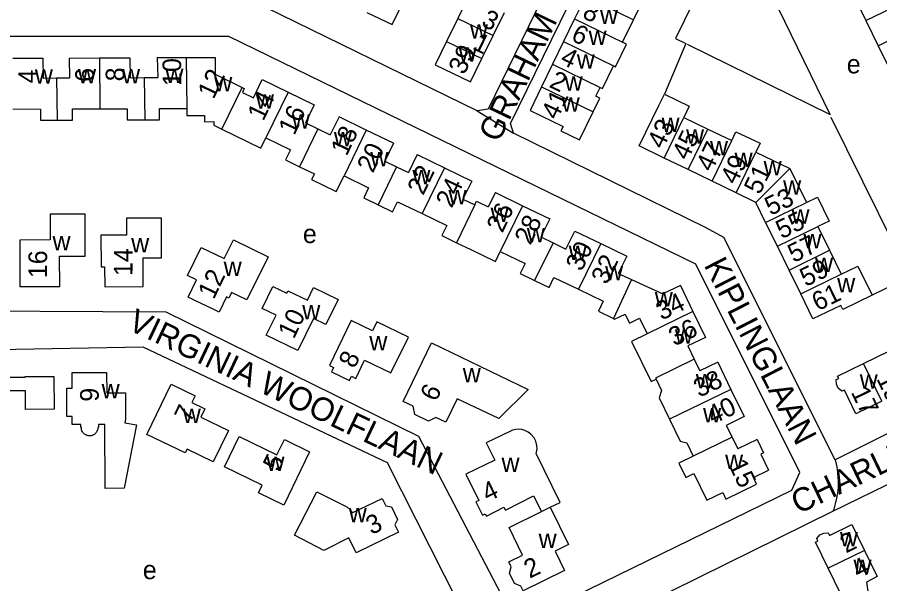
# Model space of a CAD drawing. Extents: x 159441 to 162086, y 388175 to 389787.
# Drawn here: x 161138.4 to 161323.2, y 388573.1 to 388694.6 of the extents above; entities that cross this region are included whole.
import ezdxf

# ---------------------------------------------------------------- set-up
doc = ezdxf.new("R2010")
doc.units = 0
for name, color, linetype in [('BLT_Basislijn', 7, 'Continuous'), ('BLT_Bebouwing', 7, 'Continuous'), ('BLT_Centroide', 7, 'Continuous'), ('BLT_Huisnummer', 7, 'Continuous'), ('BLT_Huisnummer_ tussenligend', 7, 'Continuous'), ('BLT_Onderverdeling_panden', 7, 'Continuous'), ('BLT_Straatnaam', 7, 'Continuous'), ('BLT_Vlakafsluiter', 7, 'Continuous')]:
    doc.layers.add(name, color=color, linetype=linetype)

msp = doc.modelspace()

# ---------------------------------------------------------------- linework, layer by layer
at = {"layer": 'BLT_Basislijn'}
for p, q in [((161165.42, 388623.86), (161116.75, 388622.95)), ((161217.72, 388599.05), (161165.42, 388623.86)), ((161335.21, 388610.56), (161313.61, 388599.68)), ((161237.07, 388560.94), (161217.72, 388599.05)), ((161313.14, 388588.69), (161333.92, 388598.92)), ((161221.35, 388543.5), (161313.14, 388588.69))]:
    msp.add_line(p, q, dxfattribs=at)
for points in [[(161177.47, 388769.07), (161262.68, 388728.15), (161263.71, 388725.06), (161239.32, 388674.86), (161236.91, 388674.52)], [(161244.74, 388669.73), (161244.06, 388671.79), (161276.02, 388737.08), (161304.54, 388751.51)], [(161306.86, 388721.18), (161290.99, 388713.73), (161279.44, 388690.03), (161281.62, 388688.97), (161277.05, 388678.12)], [(161281.96, 388688.8), (161312.54, 388673.75), (161293.12, 388713.67)], [(161236.91, 388674.52), (161188.46, 388698.24), (161178.16, 388699.61), (161118.37, 388699.27)], [(161245.45, 388564.44), (161304.37, 388593.21), (161306.09, 388596.99), (161283.75, 388641.67), (161183.73, 388690.48), (161116.02, 388690.48)], [(161312.73, 388673.16), (161329.64, 388638.96), (161321.54, 388635)], [(161313.61, 388599.68), (161289.76, 388647.39), (161285.98, 388649.45), (161244.74, 388669.73)], [(161116.31, 388631.73), (161170.26, 388631.42), (161224.37, 388604.8), (161245.45, 388564.44)], [(161313.61, 388599.68), (161313.9, 388598.53), (161314.1, 388597.36), (161314.23, 388596.18), (161314.27, 388595), (161314.24, 388593.81), (161314.13, 388592.63), (161313.93, 388591.46), (161313.66, 388590.3), (161313.32, 388589.17), (161313.14, 388588.69)]]:
    msp.add_lwpolyline(points, dxfattribs=at)
at = {"layer": 'BLT_Bebouwing'}
for p, q in [((161235.19, 388699.3), (161232.79, 388694.35)), ((161260.17, 388699.11), (161257.81, 388694.26)), ((161317.56, 388699.28), (161320.2, 388693.88)), ((161240.37, 388690.67), (161242.77, 388695.62)), ((161232.79, 388694.35), (161230.39, 388689.4)), ((161257.81, 388694.26), (161255.46, 388689.41)), ((161320.2, 388693.88), (161322.83, 388688.49)), ((161237.97, 388685.72), (161240.37, 388690.67)), ((161255.46, 388689.41), (161253.09, 388684.54)), ((161322.83, 388688.49), (161325.46, 388683.1)), ((161137.45, 388685.81), (161143.93, 388685.83)), ((161143.93, 388685.83), (161144, 388681.54)), ((161149.55, 388685.86), (161156.04, 388685.88)), ((161149.55, 388685.86), (161149.64, 388681.63)), ((161156.04, 388685.88), (161162.54, 388685.91)), ((161162.54, 388685.91), (161162.62, 388681.62)), ((161168.42, 388685.95), (161174.63, 388685.96)), ((161168.42, 388685.95), (161168.54, 388681.71)), ((161174.63, 388685.96), (161180.83, 388685.97)), ((161180.83, 388685.97), (161180.85, 388682.37)), ((161253.09, 388684.54), (161250.72, 388679.67)), ((161180.85, 388682.37), (161186.61, 388679.53)), ((161144, 388681.54), (161146.82, 388681.58)), ((161146.82, 388681.58), (161149.64, 388681.63)), ((161162.62, 388681.62), (161165.58, 388681.66)), ((161165.58, 388681.66), (161168.54, 388681.71)), ((161189.01, 388677.33), (161190.88, 388681.23)), ((161190.88, 388681.23), (161196.45, 388678.53)), ((161186.61, 388679.53), (161187.06, 388679.32)), ((161187.06, 388679.32), (161186.65, 388678.49)), ((161186.65, 388678.49), (161189.01, 388677.33)), ((161196.45, 388678.53), (161202.01, 388675.82)), ((161202.01, 388675.82), (161200.15, 388671.96)), ((161207.35, 388673.25), (161205.48, 388669.39)), ((161213.19, 388670.42), (161207.35, 388673.25)), ((161281.23, 388673.09), (161286.36, 388670.62)), ((161200.15, 388671.96), (161202.82, 388670.68)), ((161202.82, 388670.68), (161205.48, 388669.39)), ((161219.03, 388667.58), (161213.19, 388670.42)), ((161286.36, 388670.62), (161291.46, 388668.16)), ((161219.03, 388667.58), (161217.16, 388663.72)), ((161296.61, 388665.69), (161303.91, 388662.17)), ((161217.16, 388663.72), (161219.69, 388662.5)), ((161224.09, 388665.14), (161222.22, 388661.28)), ((161224.09, 388665.14), (161229.93, 388662.3)), ((161282.14, 388661.93), (161277.02, 388664.41)), ((161219.69, 388662.5), (161222.22, 388661.28)), ((161229.93, 388662.3), (161235.77, 388659.46)), ((161287.27, 388659.44), (161282.14, 388661.93)), ((161303.91, 388662.17), (161307.46, 388654.86)), ((161235.77, 388659.46), (161233.89, 388655.61)), ((161292.4, 388656.95), (161287.27, 388659.44)), ((161240.84, 388657.04), (161239.31, 388653.93)), ((161240.84, 388657.04), (161246.67, 388654.2)), ((161296.66, 388654.88), (161292.4, 388656.95)), ((161233.89, 388655.61), (161236.42, 388654.4)), ((161298.74, 388650.62), (161296.66, 388654.88)), ((161246.67, 388654.2), (161252.51, 388651.37)), ((161252.51, 388651.37), (161250.61, 388647.53)), ((161301.24, 388645.51), (161298.74, 388650.62)), ((161255.9, 388644.88), (161257.87, 388648.77)), ((161257.87, 388648.77), (161263.43, 388646.07)), ((161309.95, 388649.73), (161312.42, 388644.64)), ((161250.61, 388647.53), (161253.25, 388646.2)), ((161253.25, 388646.2), (161255.9, 388644.88)), ((161263.43, 388646.07), (161268.99, 388643.37)), ((161303.74, 388640.39), (161301.24, 388645.51)), ((161268.99, 388643.37), (161267.18, 388639.69)), ((161312.42, 388644.64), (161314.91, 388639.51)), ((161267.18, 388639.69), (161270, 388638.39)), ((161306.25, 388635.27), (161303.74, 388640.39)), ((161270, 388638.39), (161276.71, 388635.29)), ((161258.67, 388636.27), (161263.94, 388633.71)), ((161280.49, 388637.11), (161276.71, 388635.29)), ((161280.49, 388637.11), (161283.17, 388631.53)), ((161283.17, 388631.53), (161285.86, 388625.95)), ((161285.86, 388625.95), (161282.06, 388624.12)), ((161282.06, 388624.12), (161283.42, 388621.32)), ((161319.7, 388620.4), (161325.09, 388623.04)), ((161283.42, 388621.32), (161284.63, 388618.8)), ((161288.46, 388620.63), (161284.63, 388618.8)), ((161288.46, 388620.63), (161291.3, 388614.8)), ((161314.13, 388617.68), (161319.7, 388620.4)), ((161241.57, 388608.57), (161247.89, 388614.76)), ((161278.16, 388608.41), (161280.42, 388603.75)), ((161290.31, 388607.1), (161291.54, 388604.57)), ((161291.54, 388604.57), (161292.78, 388602.04)), ((161296.9, 388604.05), (161292.78, 388602.04)), ((161317.21, 388585.84), (161319.92, 388580.31))]:
    msp.add_line(p, q, dxfattribs=at)
for points in [[(161213.33, 388695.64), (161218.7, 388693.04), (161222.92, 388701.75)], [(161270.42, 388694.07), (161272.78, 388698.93)], [(161268.07, 388689.23), (161270.42, 388694.07)], [(161230.39, 388689.4), (161227.97, 388684.4), (161235.55, 388680.73), (161237.97, 388685.72)], [(161266.11, 388684.17), (161266.59, 388683.94), (161268.93, 388688.81), (161268.07, 388689.23)], [(161263.28, 388679.57), (161263.76, 388679.33), (161266.11, 388684.17)], [(161250.72, 388679.67), (161248.26, 388674.61), (161255.33, 388671.17), (161254.88, 388670.26), (161258.87, 388668.35), (161261.76, 388674.3)], [(161261.76, 388674.3), (161263.21, 388677.27), (161262.37, 388677.68), (161263.28, 388679.57)], [(161275.86, 388675.67), (161277.05, 388678.12), (161282.34, 388675.55), (161281.23, 388673.09)], [(161137.49, 388674.95), (161143.38, 388674.92), (161143.39, 388672.52), (161146.97, 388672.53)], [(161146.97, 388672.53), (161150.26, 388672.54), (161150.25, 388674.94), (161156.09, 388674.96)], [(161156.09, 388674.96), (161161.99, 388674.98), (161162, 388672.58), (161165.72, 388672.59)], [(161165.72, 388672.59), (161168.89, 388672.6), (161168.88, 388675), (161174.73, 388675.02)], [(161174.73, 388675.02), (161174.74, 388673.5), (161178.52, 388673.51), (161178.52, 388672.21), (161180.57, 388672.22), (161180.57, 388671.43), (161182.23, 388670.63)], [(161277.02, 388664.41), (161271.65, 388667.02), (161275.86, 388675.67)], [(161182.23, 388670.63), (161190.62, 388666.56), (161191.67, 388668.72)], [(161291.46, 388668.16), (161292.37, 388670.05), (161297.53, 388667.58), (161296.61, 388665.69)], [(161191.67, 388668.72), (161196.94, 388666.17), (161195.9, 388664.01), (161198.9, 388662.55)], [(161198.9, 388662.55), (161202.08, 388661.01), (161201.49, 388659.78), (161206.75, 388657.23), (161208.43, 388660.6)], [(161208.43, 388660.6), (161213.69, 388658.05), (161212.65, 388655.9), (161215.77, 388654.38)], [(161215.77, 388654.38), (161218.83, 388652.9), (161219.88, 388655.06), (161225.16, 388652.5)], [(161236.42, 388654.4), (161236.77, 388655.14), (161239.31, 388653.93)], [(161307.46, 388654.86), (161309.86, 388656.02), (161312.34, 388650.91), (161309.95, 388649.73)], [(161139, 388636.84), (161147.54, 388636.87), (161147.51, 388643.36), (161152.99, 388643.37), (161152.97, 388652.4), (161145.46, 388652.38), (161145.48, 388646.89), (161138.98, 388646.84), (161139, 388636.84)], [(161225.16, 388652.5), (161230.44, 388649.94), (161229.4, 388647.78), (161232.53, 388646.27)], [(161156.31, 388647.91), (161156.4, 388641.12), (161157.14, 388641.08), (161157.16, 388636.81), (161165.39, 388636.84), (161165.37, 388643.02), (161169.33, 388643.01), (161169.34, 388651.52), (161161.84, 388651.53), (161161.83, 388647.9), (161156.31, 388647.91)], [(161184.75, 388646.89), (161192.15, 388643.25), (161187.62, 388633.98), (161184.34, 388635.56), (161183.76, 388634.37), (161183.27, 388634.63), (161181.69, 388631.37), (161180.11, 388632.13), (161176.62, 388633.8), (161175.07, 388634.57), (161176.84, 388638.3), (161174.87, 388639.26), (161177.83, 388645.27), (161182.76, 388642.85), (161184.75, 388646.89)], [(161232.53, 388646.27), (161235.58, 388644.79), (161240.86, 388642.23)], [(161240.86, 388642.23), (161241.9, 388644.39)], [(161241.9, 388644.39), (161247.19, 388641.83), (161246.15, 388639.67), (161249.24, 388638.17)], [(161314.91, 388639.51), (161318.51, 388641.25), (161321.54, 388635), (161315.25, 388631.92), (161314.81, 388632.82), (161308.87, 388629.91), (161306.25, 388635.27)], [(161249.24, 388638.17), (161252.33, 388636.67), (161253.38, 388638.83), (161258.67, 388636.27)], [(161191.78, 388626.43), (161193.87, 388630.74), (161190.92, 388632.17), (161193.2, 388636.89), (161196.15, 388635.45), (161196.41, 388635.98), (161200.59, 388633.94), (161201.9, 388636.65), (161207.17, 388634.1), (161204.53, 388628.7), (161201.85, 388630.01), (161198.54, 388623.18), (161191.78, 388626.43)], [(161263.94, 388633.71), (161262.9, 388631.56), (161266.12, 388629.99)], [(161266.12, 388629.99), (161266.39, 388629.87), (161268.61, 388630.96), (161269.58, 388629), (161271.73, 388630.05), (161273.35, 388626.74)], [(161209.98, 388629.6), (161205.29, 388619.91), (161206.16, 388619.48), (161205.77, 388618.6), (161209.59, 388616.74), (161210.01, 388617.62), (161210.92, 388617.18), (161212.78, 388621.05), (161218.44, 388618.33), (161222.21, 388625.98), (161215.46, 388629.28), (161214.53, 388627.38), (161209.98, 388629.6)], [(161273.35, 388626.74), (161270.02, 388625.1), (161274.24, 388616.5), (161275.25, 388616.99)], [(161241.57, 388608.57), (161232.65, 388612.82), (161230.26, 388607.81), (161228.12, 388608.82), (161226.49, 388608.03), (161223.62, 388609.42), (161223.23, 388611.2), (161221.06, 388612.25), (161227.15, 388624.81), (161247.89, 388614.76)], [(161121.56, 388618.35), (161135.4, 388618.4), (161135.42, 388617.41), (161140.14, 388617.44), (161140.15, 388617.56), (161146.29, 388617.58), (161146.32, 388610.54), (161140.18, 388610.51), (161140.16, 388614.54), (161135.43, 388614.52), (161135.45, 388609.07), (161121.61, 388608.99), (161121.56, 388618.35)], [(161150.22, 388607.28), (161150.22, 388609.03), (161149.07, 388609.03), (161149.04, 388615.08), (161150.21, 388615.09), (161150.2, 388618.43)], [(161150.2, 388618.43), (161157.57, 388618.47), (161157.59, 388614.07), (161161.59, 388614.09), (161161.62, 388608.94)], [(161323.65, 388612.32), (161318.08, 388609.59), (161315.6, 388614.66), (161315.06, 388614.4), (161314.3, 388615.05), (161313.88, 388615.9), (161313.84, 388616.91), (161314.38, 388617.17), (161314.13, 388617.68)], [(161171.4, 388615.9), (161176.54, 388613.4), (161175.85, 388611.97), (161178.63, 388610.62), (161177.77, 388608.84), (161183.65, 388606.02), (161180.39, 388599.27), (161180.39, 388599.27), (161174.79, 388602), (161174.4, 388601.18), (161166.18, 388605.11), (161171.4, 388615.9)], [(161275.25, 388616.99), (161276.44, 388614.57), (161275.92, 388612.98), (161278.16, 388608.41)], [(161291.3, 388614.8), (161294.15, 388608.98), (161290.31, 388607.1)], [(161161.62, 388608.94), (161161.62, 388608.42), (161161.46, 388607.64), (161163.96, 388607.21), (161161.34, 388593.62), (161157.26, 388593.6), (161157.19, 388607.29)], [(161157.19, 388607.29), (161155.83, 388607.28), (161155.83, 388606.61), (161155.69, 388606.61), (161155.67, 388606.31), (161155.58, 388605.98), (161155.5, 388605.8), (161155.4, 388605.64), (161155.28, 388605.47), (161155.18, 388605.37), (161155.06, 388605.25), (161154.91, 388605.14), (161154.74, 388605.04), (161154.58, 388604.96), (161154.41, 388604.91), (161154.24, 388604.86), (161153.94, 388604.84), (161153.76, 388604.85), (161153.6, 388604.87), (161153.44, 388604.91), (161153.31, 388604.95), (161153.11, 388605.04), (161153, 388605.11), (161152.86, 388605.2), (161152.76, 388605.29), (161152.59, 388605.46), (161152.49, 388605.59), (161152.39, 388605.75), (161152.29, 388605.95), (161152.22, 388606.16), (161152.2, 388606.3), (161152.17, 388606.46), (161152.17, 388606.61), (161152.03, 388606.61), (161152.02, 388607.28), (161150.22, 388607.28)], [(161252.59, 388589.54), (161254.71, 388590.58), (161249.58, 388601.05), (161249.67, 388601.35), (161249.77, 388602.07), (161249.73, 388602.78), (161249.5, 388603.72), (161249.12, 388604.44), (161248.47, 388605.21), (161247.85, 388605.67), (161247.15, 388606), (161246.5, 388606.18), (161245.85, 388606.26), (161245.22, 388606.22), (161244.52, 388606.07), (161243.92, 388605.81)], [(161195.68, 388604.08), (161201.06, 388601.46), (161195.52, 388590.01), (161190.11, 388592.64), (161190.9, 388594.27), (161182.81, 388598.19), (161185.95, 388604.68), (161194.03, 388600.77), (161195.68, 388604.08)], [(161243.92, 388605.81), (161238.88, 388603.36), (161240.7, 388599.65)], [(161280.42, 388603.75), (161281.84, 388603.39), (161283.22, 388600.53)], [(161296.9, 388604.05), (161298.3, 388601.2), (161297.7, 388600.9), (161299.37, 388597.49)], [(161240.7, 388599.65), (161234.55, 388596.62), (161237.29, 388591.02), (161236.68, 388590.69), (161238.08, 388587.86), (161238.68, 388588.14), (161238.93, 388587.64), (161242.69, 388589.54), (161243.01, 388588.91), (161249.03, 388591.96), (161250.7, 388588.62)], [(161283.22, 388600.53), (161280.14, 388599.02), (161281.65, 388595.92), (161283.36, 388596.76), (161286.17, 388591.04), (161289.54, 388592.7), (161290.23, 388591.31), (161296.79, 388594.53), (161296.12, 388595.91), (161299.37, 388597.49)], [(161209.44, 388582.96), (161204.07, 388580.3), (161197.82, 388583.56), (161202.62, 388592.87)], [(161202.62, 388592.87), (161209.02, 388589.62), (161209.27, 388589.45), (161209.49, 388589.27), (161209.68, 388589.1), (161209.87, 388588.88), (161209.99, 388588.7), (161210.1, 388588.53), (161210.2, 388588.32)], [(161210.2, 388588.32), (161216.59, 388591.42), (161217.41, 388589.82), (161218.6, 388589.61), (161219.9, 388586.9), (161219.33, 388585.77), (161220.09, 388584.22), (161211, 388579.8), (161209.44, 388582.96)], [(161252.59, 388589.54), (161256.51, 388581.54), (161253.63, 388580.14), (161255.66, 388575.98), (161246.78, 388571.62), (161246.29, 388572.66), (161244.97, 388573.22), (161243.89, 388575.4), (161244.24, 388576.78), (161243.72, 388577.84), (161246.68, 388579.29), (161243.78, 388585.23), (161250.7, 388588.62)], [(161312.1, 388576.49), (161309.4, 388582.03), (161309.94, 388582.3), (161309.68, 388582.83), (161310.35, 388583.6), (161311.19, 388584.01), (161312.16, 388584.04), (161312.44, 388583.51), (161317.21, 388585.84)], [(161319.92, 388580.31), (161322.64, 388574.72), (161320.32, 388573.47), (161320.7, 388571.09)], [(161314.96, 388570.15), (161314.82, 388570.92), (161312.1, 388576.49)]]:
    msp.add_lwpolyline(points, dxfattribs=at)
at = {"layer": 'BLT_Onderverdeling_panden'}
for p, q in [((161260.17, 388699.11), (161270.42, 388694.07)), ((161320.2, 388693.88), (161328.15, 388697.77)), ((161232.79, 388694.35), (161240.37, 388690.67)), ((161257.81, 388694.26), (161268.07, 388689.23)), ((161322.83, 388688.49), (161330.78, 388692.38)), ((161230.39, 388689.4), (161237.97, 388685.72)), ((161255.46, 388689.41), (161266.11, 388684.17)), ((161156.04, 388685.88), (161156.09, 388674.96)), ((161174.63, 388685.96), (161174.73, 388675.02)), ((161253.09, 388684.54), (161263.28, 388679.57)), ((161146.82, 388681.58), (161146.97, 388672.53)), ((161165.58, 388681.66), (161165.72, 388672.59)), ((161182.23, 388670.63), (161186.61, 388679.53)), ((161196.45, 388678.53), (161191.67, 388668.72)), ((161250.72, 388679.67), (161261.76, 388674.3)), ((161277.02, 388664.41), (161281.23, 388673.09)), ((161202.82, 388670.68), (161198.9, 388662.55)), ((161213.19, 388670.42), (161208.43, 388660.6)), ((161282.14, 388661.93), (161286.36, 388670.62)), ((161287.27, 388659.44), (161291.46, 388668.16)), ((161292.4, 388656.95), (161296.61, 388665.69)), ((161219.69, 388662.5), (161215.77, 388654.38)), ((161229.93, 388662.3), (161225.16, 388652.5)), ((161296.66, 388654.88), (161303.91, 388662.17)), ((161236.42, 388654.4), (161232.53, 388646.27)), ((161298.74, 388650.62), (161307.46, 388654.86)), ((161246.67, 388654.2), (161241.9, 388644.39)), ((161301.24, 388645.51), (161309.95, 388649.73)), ((161253.25, 388646.2), (161249.24, 388638.17)), ((161263.43, 388646.07), (161258.67, 388636.27)), ((161303.74, 388640.39), (161312.42, 388644.64)), ((161306.25, 388635.27), (161314.91, 388639.51)), ((161270, 388638.39), (161266.12, 388629.99)), ((161283.17, 388631.53), (161273.35, 388626.74)), ((161323.65, 388612.32), (161319.7, 388620.4)), ((161291.3, 388614.8), (161278.16, 388608.41)), ((161291.54, 388604.57), (161283.22, 388600.53)), ((161250.7, 388588.62), (161252.59, 388589.54)), ((161319.92, 388580.31), (161312.1, 388576.49))]:
    msp.add_line(p, q, dxfattribs=at)
msp.add_lwpolyline([(161283.42, 388621.32), (161275.12, 388617.25), (161275.25, 388616.99)], dxfattribs=at)
at = {"layer": 'BLT_Vlakafsluiter'}
msp.add_line((161236.91, 388674.52), (161244.74, 388669.73), dxfattribs=at)

# ---------------------------------------------------------------- texts
at = {"layer": 'BLT_Centroide'}
for s, p in [('w', (161263.24, 388693.16)), ('w', (161235.38, 388690.03)), ('w', (161260.81, 388688.68)), ('w', (161232.98, 388685.06)), ('w', (161258.28, 388683.61)), ('e', (161316.11, 388682.56)), ('w', (161142.2, 388680.38)), ('w', (161151.45, 388680.41)), ('w', (161160.88, 388680.44)), ('w', (161170.16, 388680.47)), ('w', (161180.62, 388678.69)), ('w', (161255.68, 388678.85)), ('w', (161189.55, 388674.97)), ('w', (161255.06, 388674.38)), ('w', (161197.25, 388670.73)), ('w', (161276.44, 388670.03)), ('w', (161206.25, 388666.94)), ('w', (161281.69, 388667.52)), ('w', (161286.81, 388665.03)), ('w', (161214.06, 388662.61)), ('w', (161292.08, 388662.48)), ('w', (161298.3, 388660.7)), ('w', (161223.07, 388658.81)), ('w', (161302.48, 388656.53)), ('w', (161230.8, 388654.48)), ('w', (161239.82, 388650.72)), ('w', (161304.27, 388650.34)), ('e', (161199.61, 388646.18)), ('w', (161247.58, 388646.36)), ('w', (161145.98, 388644.62)), ('w', (161162.83, 388644.17)), ('w', (161306.83, 388645.06)), ('w', (161256.55, 388642.53)), ('w', (161182.64, 388639.12)), ('w', (161264.34, 388638.23)), ('w', (161309.32, 388639.97)), ('w', (161314.06, 388635.59)), ('w', (161274.99, 388632.59)), ('w', (161199.47, 388629.81)), ('w', (161279.31, 388624.59)), ('w', (161213.84, 388623.16)), ('w', (161233.86, 388616.31)), ('w', (161283.78, 388615.03)), ('w', (161318.89, 388615)), ('w', (161156.5, 388612.88)), ('w', (161173.88, 388607.59)), ('w', (161285.34, 388607.72)), ('w', (161290.05, 388597.78)), ('w', (161191.81, 388597.34)), ('w', (161242.16, 388597.11)), ('w', (161209.44, 388586.34)), ('w', (161314.64, 388581.19)), ('w', (161250.11, 388580.8)), ('e', (161165.32, 388574.12)), ('w', (161317.56, 388575.22))]:
    msp.add_text(s, height=4, dxfattribs=at).set_placement(p)
at = {"layer": 'BLT_Huisnummer'}
for s, rotation, p in [('8', 334.1527, (161259.24, 388694.6)), ('3', 334.1527, (161237.61, 388692.85)), ('39', 64.357, (161234.18, 388682.08)), ('4', 334.1527, (161254.49, 388684.8)), ('4', 90.2287, (161142.67, 388680.43)), ('8', 90.2287, (161161.38, 388680.87)), ('12', 64.5291, (161180.48, 388676.86)), ('41', 64.357, (161254.07, 388672.39)), ('16', 64.5291, (161197.77, 388669.12)), ('43', 64.357, (161276.77, 388666.16)), ('20', 64.5291, (161214.61, 388661.03)), ('47', 64.357, (161287.2, 388661.26)), ('51', 64.357, (161297.49, 388656.4)), ('24', 64.5291, (161231.48, 388653.52)), ('55', 26.0565, (161302.16, 388646.98)), ('28', 64.5291, (161248.34, 388645.59)), ('16', 89.809, (161144.81, 388638.66)), ('14', 89.809, (161163.11, 388639.11)), ('32', 64.5291, (161264.76, 388637.1)), ('12', 64.357, (161180.53, 388633.95)), ('61', 26.0565, (161309.88, 388631.52)), ('10', 64.357, (161197.67, 388625.44)), ('36', 25.6982, (161279.17, 388623.99)), ('8', 64.357, (161210.68, 388619.12)), ('6', 64.357, (161228.14, 388612.02)), ('9', 90.0971, (161155.89, 388612.18)), ('17', 296.0554, (161316.92, 388614.24)), ('7', 64.1976, (161175.48, 388607.53)), ('5', 64.2159, (161194.44, 388597.01)), ('15', 295.9754, (161290.67, 388598.69)), ('4', 25.6982, (161239.16, 388590.63)), ('3', 25.6065, (161214.31, 388583.56)), ('2', 26.0673, (161315.91, 388579.62)), ('2', 25.6982, (161248.17, 388574.21))]:
    msp.add_text(s, height=4, rotation=rotation, dxfattribs=at).set_placement(p)
at = {"layer": 'BLT_Huisnummer_ tussenligend'}
for s, rotation, p in [('6', 334.1527, (161256.83, 388689.74)), ('1', 334.1527, (161235.72, 388687.88)), ('10', 90.2287, (161173.56, 388679.89)), ('6', 90.2287, (161154.85, 388680.76)), ('2', 334.1527, (161252.17, 388679.73)), ('14', 64.5291, (161191.14, 388672.17)), ('18', 64.5291, (161208.98, 388664.67)), ('45', 64.357, (161282.05, 388663.72)), ('49', 64.357, (161292.42, 388658.5)), ('22', 64.5291, (161225.39, 388656.25)), ('53', 26.0565, (161299.79, 388651.99)), ('26', 64.5291, (161242.35, 388648.19)), ('57', 26.0565, (161304.72, 388641.88)), ('30', 64.5291, (161259.32, 388639.92)), ('59', 26.0565, (161307.3, 388636.74)), ('34', 25.6982, (161276.45, 388629.54)), ('38', 25.6982, (161284.51, 388613)), ('19', 296.0554, (161322.39, 388617.09)), ('40', 25.6982, (161287.44, 388607.23)), ('4', 26.0673, (161318.53, 388574.16))]:
    msp.add_text(s, height=4, rotation=rotation, dxfattribs=at).set_placement(p)
at = {"layer": 'BLT_Straatnaam'}
for s, height, rotation, p in [('GRAHAM GREENELAAN', 5, 64.409, (161241.55, 388667.53)), ('KIPLINGLAAN', 4.9999, 297.1825, (161285.42, 388641.47)), ('VIRGINIA WOOLFLAAN', 5, 334.6093, (161161.82, 388627.75)), ('CHARLES DICKENSLAAN', 5, 25.6462, (161305.72, 388587.99))]:
    msp.add_text(s, height=height, rotation=rotation, dxfattribs=at).set_placement(p)

doc.saveas('drawing.dxf')
